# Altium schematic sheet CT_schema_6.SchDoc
size 274 x 160 mm
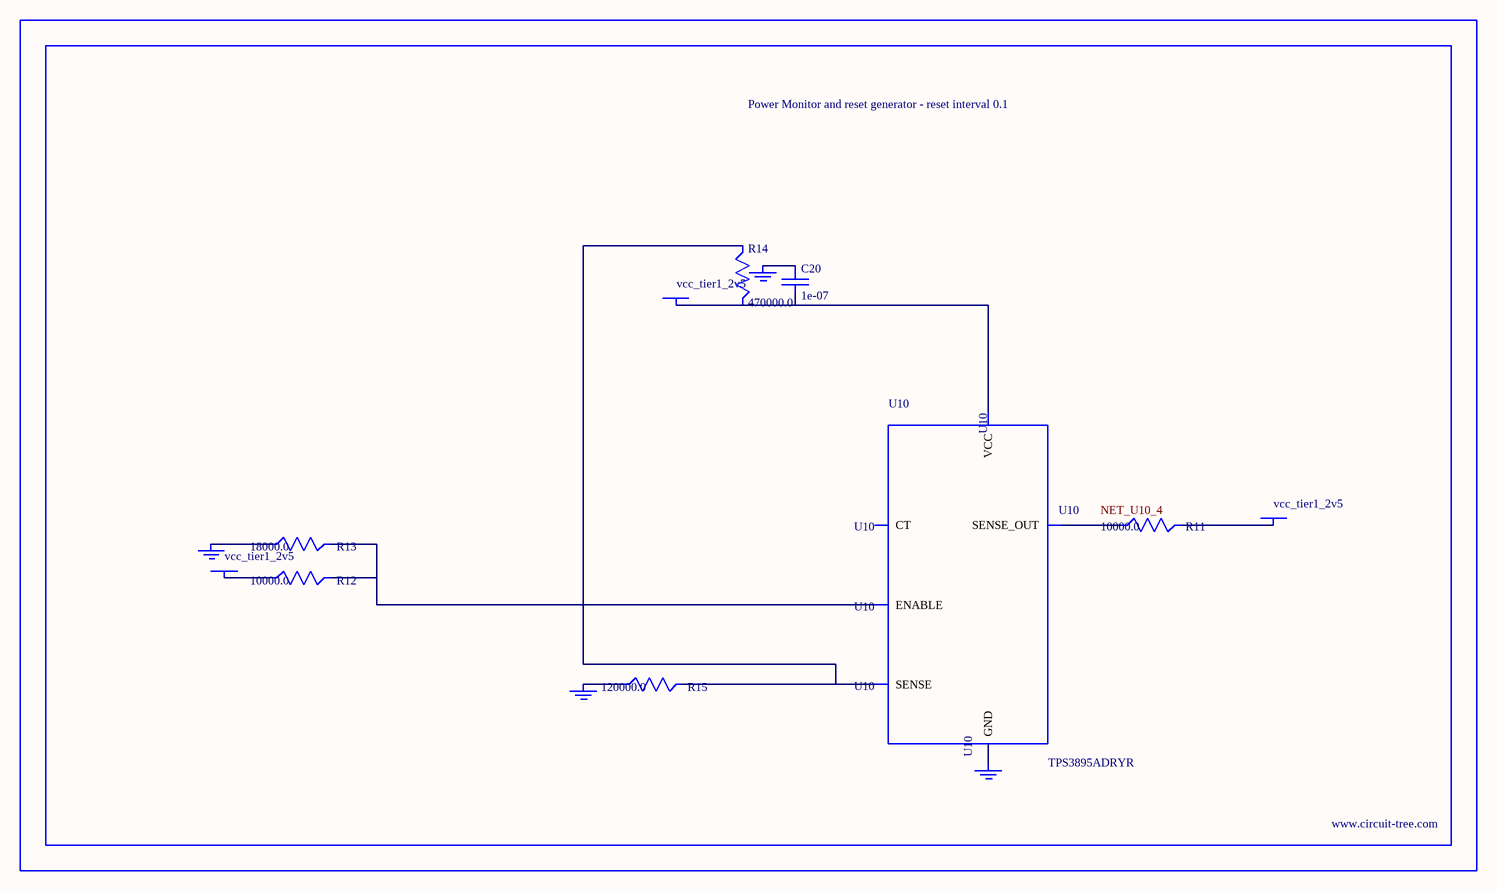
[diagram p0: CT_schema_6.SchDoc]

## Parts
BORDER5  (no value)
C20  1e-07  [C0402]
GND_INSTANCE_5_0  (no value)
GND_INSTANCE_5_1  (no value)
GND_INSTANCE_5_2  (no value)
GND_INSTANCE_5_3  (no value)
POWER_INSTANCE_5_0  vcc_tier1_2v5
POWER_INSTANCE_5_1  vcc_tier1_2v5
POWER_INSTANCE_5_2  vcc_tier1_2v5
R11  10000.0  [R0603]
R12  10000.0  [R0603]
R13  18000.0  [R0603]
R14  470000.0  [R0603]
R15  120000.0  [R0603]
U10  TPS3895ADRYR  [SON-6]

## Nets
NetC20_1: C20.1 GND_INSTANCE_5_2.0(GND)
NetC20_2: C20.2 POWER_INSTANCE_5_2.0(PWR) R14.2 U10.6(VCC)
NetGND_INSTANCE_5_0_0: GND_INSTANCE_5_0.0(GND) R13.1
NetGND_INSTANCE_5_1_0: GND_INSTANCE_5_1.0(GND) R15.1
NetGND_INSTANCE_5_3_0: GND_INSTANCE_5_3.0(GND) U10.2(GND)
NetPOWER_INSTANCE_5_0_0: POWER_INSTANCE_5_0.0(PWR) R12.1
NetPOWER_INSTANCE_5_1_0: POWER_INSTANCE_5_1.0(PWR) R11.2
NetR11_1: R11.1 U10.4(SENSE_OUT)
NetR12_2: R12.2 R13.2 U10.1(ENABLE)
NetR14_1: R14.1 R15.2 U10.3(SENSE)

Not connected (* = marked no-connect by the designer): U10 5(CT)

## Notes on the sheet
- Labels drawn without touching a wire or pin: NET_U10_4

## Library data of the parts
BORDER5 = BORDER_PAGE5
C20 = C0402C104K3RACTU
GND_INSTANCE_5_0-GND_INSTANCE_5_3 = GND
POWER_INSTANCE_5_0-POWER_INSTANCE_5_2 = PWR
R11 R12 = RC0603JR-0710KL
R13 = RC0603JR-0718KL
R14 = RC0603JR-07470KL
R15 = RC0603JR-07120KL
